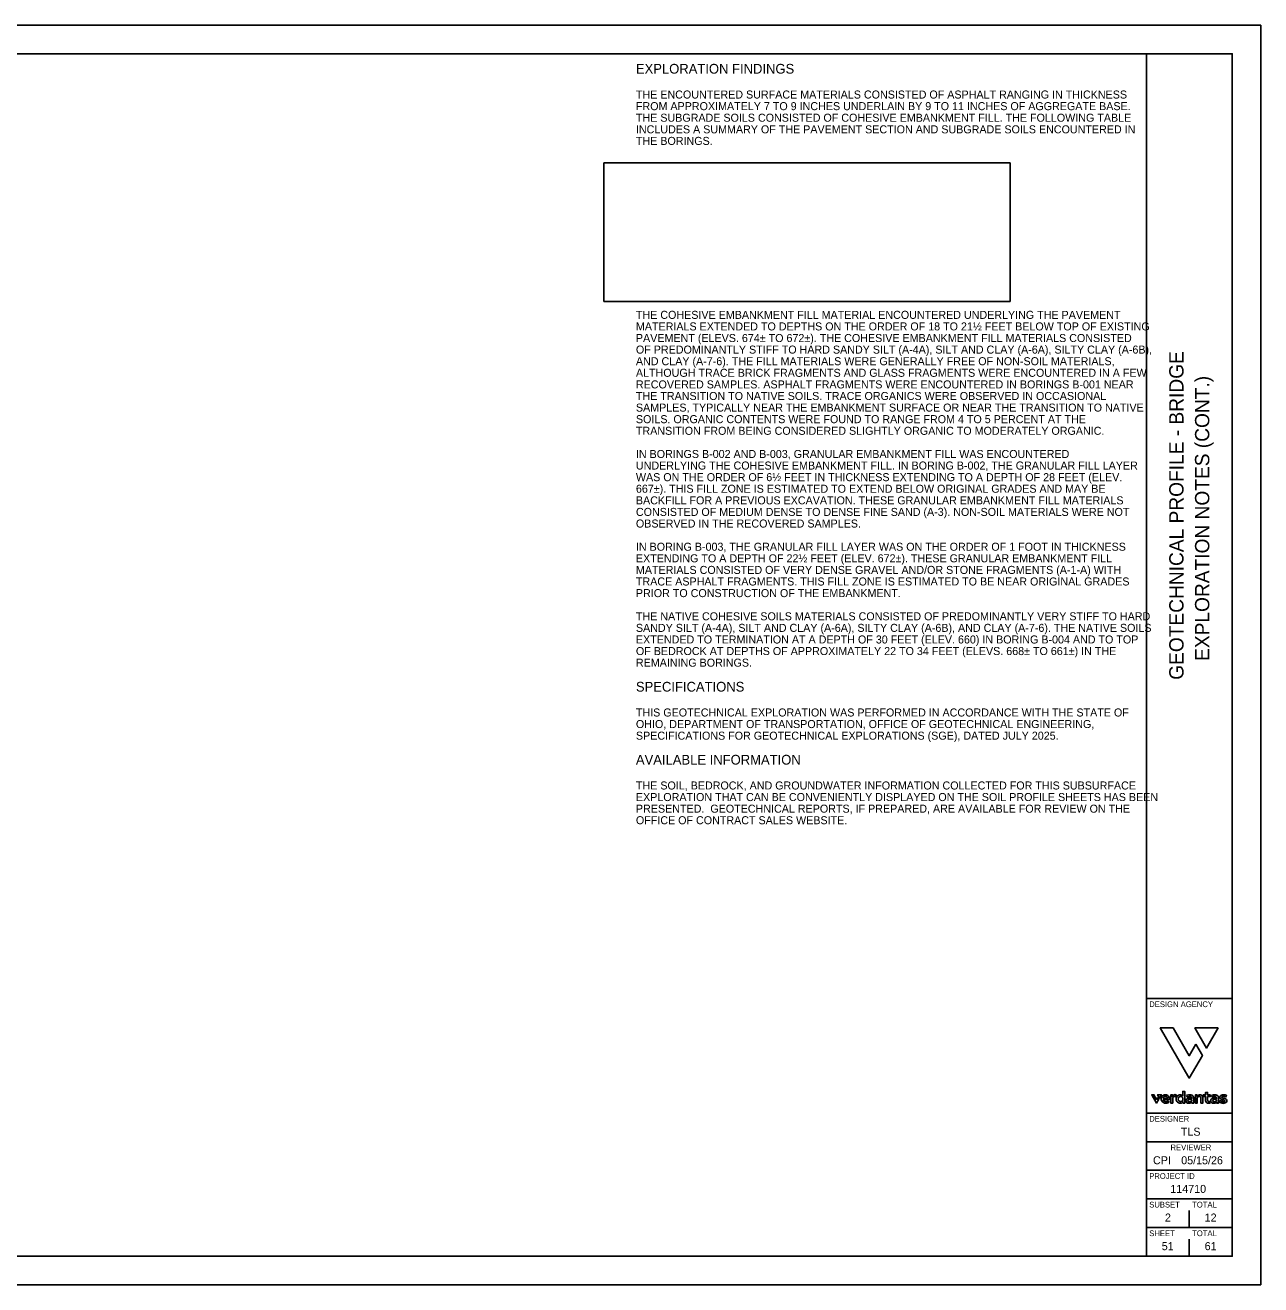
# Model space of a CAD drawing. Extents: x -59.1 to 34, y 0 to 22.
# Drawn here: x 12.41 to 34, y 0 to 22 of the extents above; entities that cross this region are included whole.
import ezdxf

# ---------------------------------------------------------------- set-up
doc = ezdxf.new("R2010")
doc.units = 0
for name, color, linetype in [('Default', 7, 'Continuous'), ('SH_Border', 7, 'Continuous'), ('SH_Cut_Line', 7, 'Continuous'), ('SH_Data', 7, 'Continuous'), ('SH_Text', 7, 'Continuous')]:
    doc.layers.add(name, color=color, linetype=linetype)

msp = doc.modelspace()

# ---------------------------------------------------------------- linework, layer by layer
at = {"layer": 'Default'}
msp.add_lwpolyline([(22.521, 17.177), (29.619, 17.177), (29.619, 19.594), (22.521, 19.594)], close=True, dxfattribs=at)
at = {"layer": 'SH_Border'}
for p, q in [((32, 0.5), (32, 21.5)), ((32, 5), (33.5, 5)), ((32, 3), (33.5, 3)), ((32, 2.5), (33.5, 2.5)), ((32, 2), (33.5, 2)), ((32, 1.5), (33.5, 1.5)), ((32, 1), (33.5, 1))]:
    msp.add_line(p, q, dxfattribs=at)
msp.add_lwpolyline([(1.5, 21.5), (33.5, 21.5), (33.5, 0.5), (1.5, 0.5)], close=True, dxfattribs=at)
at = {"layer": 'SH_Cut_Line'}
msp.add_lwpolyline([(0, 0), (34, 0), (34, 22), (0, 22)], close=True, dxfattribs=at)
at = {"layer": 'SH_Data'}
for p, q in [((32.75, 4), (32.75, 4)), ((32.75, 1), (32.75, 1.3)), ((32.375, 0.675), (32.375, 0.675)), ((32.75, 0.5), (32.75, 0.8))]:
    msp.add_line(p, q, dxfattribs=at)
at = {"layer": 'SH_Text'}
for p, q in [((32.509, 3.288), (32.525, 3.316)), ((32.712, 3.311), (32.703, 3.308)), ((33.146, 3.311), (33.137, 3.308)), ((33.385, 3.28), (33.402, 3.304)), ((32.292, 3.234), (32.407, 3.234)), ((32.373, 3.256), (32.293, 3.256)), ((32.396, 3.189), (32.379, 3.213)), ((32.637, 3.267), (32.637, 3.222)), ((32.793, 3.263), (32.793, 3.251)), ((32.793, 3.232), (32.793, 3.215)), ((33.119, 3.178), (33.107, 3.204)), ((33.227, 3.263), (33.227, 3.251)), ((33.227, 3.232), (33.227, 3.215)), ((33.295, 3.218), (33.276, 3.194)), ((33.332, 3.233), (33.347, 3.23)), ((33.364, 3.255), (33.34, 3.26))]:
    msp.add_line(p, q, dxfattribs=at)
for points in [[(32.866, 4.201), (32.75, 4), (32.468, 4.488), (32.243, 4.488), (32.75, 3.61), (32.979, 4.006)], [(32.199, 3.272), (32.18, 3.239), (32.133, 3.32), (32.095, 3.32), (32.18, 3.174), (32.218, 3.24)], [(32.23, 3.261), (32.196, 3.32), (32.264, 3.32)]]:
    msp.add_lwpolyline(points, close=True, dxfattribs=at)
for points in [[(32.866, 4.201), (32.75, 4), (32.468, 4.488), (32.243, 4.488), (32.75, 3.61), (32.979, 4.006), (32.866, 4.201)], [(33.257, 4.488), (32.848, 4.488), (33.053, 4.134), (33.257, 4.488)], [(32.199, 3.272), (32.18, 3.239), (32.133, 3.32), (32.095, 3.32), (32.18, 3.174), (32.218, 3.24), (32.199, 3.272)], [(32.264, 3.32), (32.196, 3.32), (32.23, 3.261), (32.264, 3.32)], [(32.458, 3.286), (32.458, 3.316), (32.427, 3.316), (32.427, 3.173), (32.46, 3.173), (32.46, 3.268)], [(32.458, 3.286), (32.458, 3.316), (32.427, 3.316), (32.427, 3.173), (32.46, 3.173), (32.46, 3.268)], [(32.509, 3.288), (32.525, 3.316)], [(32.637, 3.297), (32.637, 3.377), (32.671, 3.377), (32.671, 3.173), (32.64, 3.173), (32.64, 3.199)], [(32.64, 3.199), (32.64, 3.173), (32.671, 3.173), (32.671, 3.377), (32.637, 3.377), (32.637, 3.297)], [(32.712, 3.311), (32.703, 3.308)], [(32.703, 3.308), (32.714, 3.281), (32.721, 3.284)], [(32.703, 3.308), (32.714, 3.281), (32.721, 3.284)], [(32.887, 3.288), (32.887, 3.316), (32.856, 3.316), (32.856, 3.173), (32.89, 3.173), (32.89, 3.269)], [(32.887, 3.288), (32.887, 3.316), (32.856, 3.316), (32.856, 3.173), (32.89, 3.173), (32.89, 3.269)], [(33.07, 3.226), (33.07, 3.287), (33.116, 3.287), (33.116, 3.316), (33.07, 3.316), (33.07, 3.36), (33.036, 3.36), (33.036, 3.316), (32.991, 3.316), (33.009, 3.287), (33.036, 3.287), (33.036, 3.22)], [(33.07, 3.226), (33.07, 3.287), (33.116, 3.287), (33.116, 3.316), (33.07, 3.316), (33.07, 3.36), (33.036, 3.36), (33.036, 3.316), (32.991, 3.316), (33.009, 3.287), (33.036, 3.287), (33.036, 3.22)], [(33.146, 3.311), (33.137, 3.308)], [(33.137, 3.308), (33.148, 3.281), (33.155, 3.284)], [(33.137, 3.308), (33.148, 3.281), (33.155, 3.284)], [(33.385, 3.28), (33.402, 3.304), (33.401, 3.304)], [(32.292, 3.234), (32.407, 3.234)], [(32.293, 3.256), (32.373, 3.256)], [(32.396, 3.189), (32.379, 3.213)], [(32.637, 3.267), (32.637, 3.222)], [(32.793, 3.263), (32.793, 3.251)], [(32.793, 3.215), (32.793, 3.232)], [(32.796, 3.196), (32.796, 3.173), (32.827, 3.173), (32.827, 3.267)], [(32.796, 3.196), (32.796, 3.173), (32.827, 3.173), (32.827, 3.267)], [(32.954, 3.257), (32.954, 3.173), (32.988, 3.173), (32.988, 3.267)], [(32.954, 3.257), (32.954, 3.173), (32.988, 3.173), (32.988, 3.267)], [(33.119, 3.178), (33.107, 3.204)], [(33.227, 3.263), (33.227, 3.251)], [(33.227, 3.215), (33.227, 3.232)], [(33.23, 3.196), (33.23, 3.173), (33.261, 3.173), (33.261, 3.267)], [(33.23, 3.196), (33.23, 3.173), (33.261, 3.173), (33.261, 3.267)], [(33.296, 3.216), (33.295, 3.218), (33.276, 3.194), (33.279, 3.192)], [(33.332, 3.233), (33.347, 3.23)], [(33.364, 3.255), (33.34, 3.26)], [(33.383, 3.281), (33.385, 3.28)]]:
    msp.add_lwpolyline(points, dxfattribs=at)
for centre, radius, start, end in [((32.333, 3.245), 0.0747, 351.0446, 190.2577), ((32.333, 3.245), 0.0747, 351.0446, 190.2577), ((32.504, 3.274), 0.0471, 62.6524, 165.2929), ((32.504, 3.274), 0.0471, 62.6524, 165.2929), ((32.595, 3.245), 0.075, 92.7719, 272.9779), ((32.595, 3.245), 0.075, 92.7719, 272.9779), ((32.593, 3.266), 0.0536, 34.2843, 91.2723), ((32.593, 3.266), 0.0536, 34.2843, 91.2723), ((32.763, 3.171), 0.149, 90.9467, 109.8354), ((32.763, 3.171), 0.149, 90.9467, 109.8354), ((32.762, 3.224), 0.0962, 70.8128, 90.9317), ((32.762, 3.224), 0.0962, 70.8128, 90.9317), ((32.779, 3.269), 0.0479, 358.076, 72.8642), ((32.779, 3.269), 0.0479, 358.076, 72.8642), ((32.936, 3.268), 0.0527, 358.9896, 156.9111), ((32.936, 3.268), 0.0527, 358.9896, 156.9111), ((33.197, 3.171), 0.149, 90.9467, 109.8354), ((33.197, 3.171), 0.149, 90.9467, 109.8354), ((33.196, 3.224), 0.0962, 70.8128, 90.9317), ((33.196, 3.224), 0.0962, 70.8128, 90.9317), ((33.213, 3.269), 0.0479, 358.076, 72.8642), ((33.213, 3.269), 0.0479, 358.076, 72.8642), ((33.332, 3.267), 0.0503, 113.3692, 147.807), ((33.332, 3.267), 0.0503, 113.3692, 147.807), ((33.346, 3.235), 0.0854, 89.0109, 113.56), ((33.347, 3.233), 0.0867, 89.2017, 113.3692), ((33.348, 3.221), 0.0985, 57.2233, 89.842), ((33.348, 3.222), 0.0979, 56.3984, 89.8856), ((32.342, 3.255), 0.0854, 195.6668, 309.3699), ((32.342, 3.255), 0.0854, 195.6668, 309.3699), ((32.343, 3.253), 0.054, 200.9232, 312.7391), ((32.343, 3.253), 0.054, 200.9232, 312.7391), ((32.333, 3.25), 0.0407, 8.8378, 171.1622), ((32.333, 3.25), 0.0407, 8.8378, 171.1622), ((32.496, 3.249), 0.0409, 72.1384, 152.0408), ((32.496, 3.249), 0.0409, 72.1384, 152.0408), ((32.6, 3.245), 0.0446, 86.4529, 275.055), ((32.6, 3.245), 0.0446, 86.4529, 275.055), ((32.594, 3.22), 0.0503, 275.3084, 334.5252), ((32.594, 3.22), 0.0503, 275.3084, 334.5252), ((32.599, 3.246), 0.0439, 29.9007, 85.5797), ((32.599, 3.246), 0.0439, 29.9007, 85.5797), ((32.599, 3.244), 0.0441, 276.0666, 330.041), ((32.599, 3.244), 0.0441, 276.0666, 330.041), ((32.736, 3.216), 0.0444, 111.6764, 249.7268), ((32.736, 3.216), 0.0444, 111.6764, 249.7268), ((32.751, 3.182), 0.0814, 58.3497, 112.4708), ((32.751, 3.182), 0.0814, 58.3497, 112.4708), ((32.744, 3.234), 0.0643, 248.2774, 323.7949), ((32.744, 3.234), 0.0643, 248.2774, 323.7949), ((32.762, 3.177), 0.114, 91.6616, 110.8714), ((32.762, 3.177), 0.114, 91.6616, 110.8714), ((32.747, 3.218), 0.021, 92.327, 265.3778), ((32.747, 3.218), 0.021, 92.327, 265.3778), ((32.759, 3.162), 0.0786, 63.8372, 98.8746), ((32.759, 3.162), 0.0786, 63.8372, 98.8746), ((32.755, 3.244), 0.0478, 258.1247, 322.3678), ((32.755, 3.244), 0.0478, 258.1247, 322.3678), ((32.758, 3.242), 0.0486, 73.2522, 89.9971), ((32.758, 3.242), 0.0486, 73.2522, 89.9971), ((32.765, 3.262), 0.0281, 2.9671, 75.223), ((32.765, 3.262), 0.0281, 2.9671, 75.223), ((32.922, 3.254), 0.0358, 90.3466, 154.9113), ((32.922, 3.254), 0.0358, 90.3466, 154.9113), ((32.924, 3.257), 0.0325, 47.3049, 92.9688), ((32.924, 3.257), 0.0325, 47.3049, 92.9688), ((32.922, 3.259), 0.0325, 356.9739, 42.7421), ((32.922, 3.259), 0.0325, 356.9739, 42.7421), ((33.084, 3.218), 0.0482, 177.8641, 271.6213), ((33.084, 3.218), 0.0482, 177.8641, 271.6213), ((33.094, 3.224), 0.0236, 175.0692, 266.3548), ((33.094, 3.224), 0.0236, 175.0692, 266.3548), ((33.086, 3.24), 0.0704, 269.5424, 298.2495), ((33.086, 3.24), 0.0704, 269.5424, 298.2495), ((33.091, 3.232), 0.0324, 271.8638, 299.9651), ((33.091, 3.232), 0.0324, 271.8638, 299.9651), ((33.17, 3.216), 0.0444, 111.6764, 249.7268), ((33.17, 3.216), 0.0444, 111.6764, 249.7268), ((33.184, 3.182), 0.0814, 58.3497, 112.4708), ((33.184, 3.182), 0.0814, 58.3497, 112.4708), ((33.178, 3.234), 0.0643, 248.2774, 323.7949), ((33.178, 3.234), 0.0643, 248.2774, 323.7949), ((33.196, 3.177), 0.114, 91.6616, 110.8714), ((33.196, 3.177), 0.114, 91.6616, 110.8714), ((33.181, 3.218), 0.021, 92.327, 265.3778), ((33.181, 3.218), 0.021, 92.327, 265.3778), ((33.189, 3.244), 0.0478, 258.1247, 322.3678), ((33.189, 3.244), 0.0478, 258.1247, 322.3678), ((33.192, 3.162), 0.0786, 63.8372, 98.8746), ((33.192, 3.162), 0.0786, 63.8372, 98.8746), ((33.192, 3.242), 0.0486, 73.2522, 89.9971), ((33.192, 3.242), 0.0486, 73.2522, 89.9971), ((33.199, 3.262), 0.0281, 2.9671, 75.223), ((33.199, 3.262), 0.0281, 2.9671, 75.223), ((33.34, 3.266), 0.0958, 227.8814, 270.5651), ((33.34, 3.267), 0.0971, 230.5166, 270.4341), ((33.319, 3.276), 0.0344, 148.9453, 227.6829), ((33.319, 3.276), 0.0344, 148.9453, 227.6829), ((33.344, 3.268), 0.0698, 225.2875, 267.0077), ((33.347, 3.311), 0.0789, 230.1259, 259.7023), ((33.347, 3.311), 0.0789, 230.1259, 259.7023), ((33.344, 3.268), 0.0699, 227.363, 266.9244), ((33.329, 3.276), 0.0111, 134.7822, 240.4366), ((33.329, 3.276), 0.0111, 134.7822, 240.4366), ((33.339, 3.265), 0.0251, 103.8561, 133.7191), ((33.339, 3.265), 0.0251, 103.8561, 133.7191), ((33.352, 3.321), 0.0614, 242.9002, 259.3831), ((33.352, 3.321), 0.0614, 242.9002, 259.3831), ((33.347, 3.239), 0.0526, 89.0539, 105.6921), ((33.347, 3.239), 0.0526, 89.0539, 105.6921), ((33.343, 3.247), 0.0491, 267.0077, 296.3112), ((33.343, 3.247), 0.0491, 267.0077, 296.3112), ((33.343, 3.259), 0.0897, 269.0192, 292.9257), ((33.342, 3.26), 0.0904, 269.1171, 292.8278), ((33.336, 3.16), 0.0712, 68.1863, 80.6328), ((33.336, 3.16), 0.0712, 68.1863, 80.6328), ((33.346, 3.221), 0.0711, 58.1233, 88.1135), ((33.346, 3.221), 0.071, 56.2397, 88.1242), ((33.359, 3.214), 0.0124, 296.9165, 73.602), ((33.359, 3.214), 0.0124, 296.9165, 73.602), ((33.342, 3.16), 0.0972, 64.0447, 77.2149), ((33.342, 3.16), 0.0972, 64.0447, 77.2149), ((33.357, 3.226), 0.0533, 292.8278, 320.7157), ((33.357, 3.226), 0.0533, 292.8278, 320.7157), ((33.369, 3.215), 0.0369, 322.7092, 64.2166), ((33.369, 3.214), 0.037, 322.8811, 64.0447)]:
    msp.add_arc(centre, radius, start, end, dxfattribs=at)

# ---------------------------------------------------------------- texts
at = {"layer": 'SH_Data'}
for s, p in [('GEOTECHNICAL PROFILE - BRIDGE', (32.65, 10.567)), ('EXPLORATION NOTES (CONT.)', (33.1, 10.897))]:
    msp.add_text(s, height=0.25, rotation=90, dxfattribs=at).set_placement(p)
for s, height, p in [('DESIGN AGENCY', 0.1, (32.05, 4.85)), ('DESIGNER', 0.1, (32.05, 2.85)), ('TLS', 0.14, (32.603, 2.605)), ('REVIEWER', 0.1, (32.422, 2.35)), ('CPI', 0.14, (32.116, 2.105)), ('05/15/26', 0.14, (32.609, 2.105)), ('PROJECT ID', 0.1, (32.05, 1.85)), ('114710', 0.14, (32.419, 1.605)), ('SUBSET', 0.1, (32.05, 1.35)), ('TOTAL', 0.1, (32.8, 1.35)), ('2', 0.14, (32.325, 1.105)), ('12', 0.14, (33.019, 1.105)), ('SHEET', 0.1, (32.05, 0.85)), ('TOTAL', 0.1, (32.8, 0.85)), ('51', 0.14, (32.269, 0.605)), ('61', 0.14, (33.019, 0.605))]:
    msp.add_text(s, height=height, dxfattribs=at).set_placement(p)
at = {"layer": 'SH_Text'}
for s, height, p in [('EXPLORATION FINDINGS', 0.17, (23.081, 21.154)), ('THE ENCOUNTERED SURFACE MATERIALS CONSISTED OF ASPHALT RANGING IN THICKNESS ', 0.14, (23.081, 20.719)), ('FROM APPROXIMATELY 7 TO 9 INCHES UNDERLAIN BY 9 TO 11 INCHES OF AGGREGATE BASE. ', 0.14, (23.081, 20.516)), ('THE SUBGRADE SOILS CONSISTED OF COHESIVE EMBANKMENT FILL. THE FOLLOWING TABLE ', 0.14, (23.081, 20.314)), ('INCLUDES A SUMMARY OF THE PAVEMENT SECTION AND SUBGRADE SOILS ENCOUNTERED IN ', 0.14, (23.081, 20.111)), ('THE BORINGS.', 0.14, (23.081, 19.909)), ('THE COHESIVE EMBANKMENT FILL MATERIAL ENCOUNTERED UNDERLYING THE PAVEMENT ', 0.14, (23.081, 16.871)), ('MATERIALS EXTENDED TO DEPTHS ON THE ORDER OF 18 TO 21½ FEET BELOW TOP OF EXISTING ', 0.14, (23.081, 16.669)), ('PAVEMENT (ELEVS. 674± TO 672±). THE COHESIVE EMBANKMENT FILL MATERIALS CONSISTED ', 0.14, (23.081, 16.466)), ('OF PREDOMINANTLY STIFF TO HARD SANDY SILT (A-4A), SILT AND CLAY (A-6A), SILTY CLAY (A-6B), ', 0.14, (23.081, 16.264)), ('AND CLAY (A-7-6). THE FILL MATERIALS WERE GENERALLY FREE OF NON-SOIL MATERIALS, ', 0.14, (23.081, 16.061)), ('ALTHOUGH TRACE BRICK FRAGMENTS AND GLASS FRAGMENTS WERE ENCOUNTERED IN A FEW ', 0.14, (23.081, 15.859)), ('RECOVERED SAMPLES. ASPHALT FRAGMENTS WERE ENCOUNTERED IN BORINGS B-001 NEAR ', 0.14, (23.081, 15.656)), ('THE TRANSITION TO NATIVE SOILS. TRACE ORGANICS WERE OBSERVED IN OCCASIONAL ', 0.14, (23.081, 15.454)), ('SAMPLES, TYPICALLY NEAR THE EMBANKMENT SURFACE OR NEAR THE TRANSITION TO NATIVE ', 0.14, (23.081, 15.251)), ('SOILS. ORGANIC CONTENTS WERE FOUND TO RANGE FROM 4 TO 5 PERCENT AT THE ', 0.14, (23.081, 15.049)), ('TRANSITION FROM BEING CONSIDERED SLIGHTLY ORGANIC TO MODERATELY ORGANIC.', 0.14, (23.081, 14.846)), ('IN BORINGS B-002 AND B-003, GRANULAR EMBANKMENT FILL WAS ENCOUNTERED ', 0.14, (23.081, 14.441)), ('UNDERLYING THE COHESIVE EMBANKMENT FILL. IN BORING B-002, THE GRANULAR FILL LAYER ', 0.14, (23.081, 14.239)), ('WAS ON THE ORDER OF 6½ FEET IN THICKNESS EXTENDING TO A DEPTH OF 28 FEET (ELEV. ', 0.14, (23.081, 14.036)), ('667±). THIS FILL ZONE IS ESTIMATED TO EXTEND BELOW ORIGINAL GRADES AND MAY BE ', 0.14, (23.081, 13.834)), ('BACKFILL FOR A PREVIOUS EXCAVATION. THESE GRANULAR EMBANKMENT FILL MATERIALS ', 0.14, (23.081, 13.631)), ('CONSISTED OF MEDIUM DENSE TO DENSE FINE SAND (A-3). NON-SOIL MATERIALS WERE NOT ', 0.14, (23.081, 13.429)), ('OBSERVED IN THE RECOVERED SAMPLES.', 0.14, (23.081, 13.226)), ('EXTENDING TO A DEPTH OF 22½ FEET (ELEV. 672±). THESE GRANULAR EMBANKMENT FILL ', 0.14, (23.081, 12.619)), ('IN BORING B-003, THE GRANULAR FILL LAYER WAS ON THE ORDER OF 1 FOOT IN THICKNESS ', 0.14, (23.081, 12.821)), ('MATERIALS CONSISTED OF VERY DENSE GRAVEL AND/OR STONE FRAGMENTS (A-1-A) WITH ', 0.14, (23.081, 12.416)), ('TRACE ASPHALT FRAGMENTS. THIS FILL ZONE IS ESTIMATED TO BE NEAR ORIGINAL GRADES ', 0.14, (23.081, 12.214)), ('PRIOR TO CONSTRUCTION OF THE EMBANKMENT.', 0.14, (23.081, 12.011)), ('THE NATIVE COHESIVE SOILS MATERIALS CONSISTED OF PREDOMINANTLY VERY STIFF TO HARD ', 0.14, (23.081, 11.606)), ('SANDY SILT (A-4A), SILT AND CLAY (A-6A), SILTY CLAY (A-6B), AND CLAY (A-7-6). THE NATIVE SOILS ', 0.14, (23.081, 11.404)), ('EXTENDED TO TERMINATION AT A DEPTH OF 30 FEET (ELEV. 660) IN BORING B-004 AND TO TOP ', 0.14, (23.081, 11.201)), ('OF BEDROCK AT DEPTHS OF APPROXIMATELY 22 TO 34 FEET (ELEVS. 668± TO 661±) IN THE ', 0.14, (23.081, 10.999)), ('REMAINING BORINGS.', 0.14, (23.081, 10.796)), ('SPECIFICATIONS', 0.17, (23.081, 10.361)), ('THIS GEOTECHNICAL EXPLORATION WAS PERFORMED IN ACCORDANCE WITH THE STATE OF ', 0.14, (23.081, 9.926)), ('OHIO, DEPARTMENT OF TRANSPORTATION, OFFICE OF GEOTECHNICAL ENGINEERING, ', 0.14, (23.081, 9.724)), ('SPECIFICATIONS FOR GEOTECHNICAL EXPLORATIONS (SGE), DATED JULY 2025. ', 0.14, (23.081, 9.521)), ('AVAILABLE INFORMATION', 0.17, (23.081, 9.086)), ('THE SOIL, BEDROCK, AND GROUNDWATER INFORMATION COLLECTED FOR THIS SUBSURFACE ', 0.14, (23.081, 8.651)), ('EXPLORATION THAT CAN BE CONVENIENTLY DISPLAYED ON THE SOIL PROFILE SHEETS HAS BEEN ', 0.14, (23.081, 8.449)), ('PRESENTED.  GEOTECHNICAL REPORTS, IF PREPARED, ARE AVAILABLE FOR REVIEW ON THE ', 0.14, (23.081, 8.246)), ('OFFICE OF CONTRACT SALES WEBSITE.', 0.14, (23.081, 8.044))]:
    msp.add_text(s, height=height, dxfattribs=at).set_placement(p)

doc.saveas('drawing.dxf')
